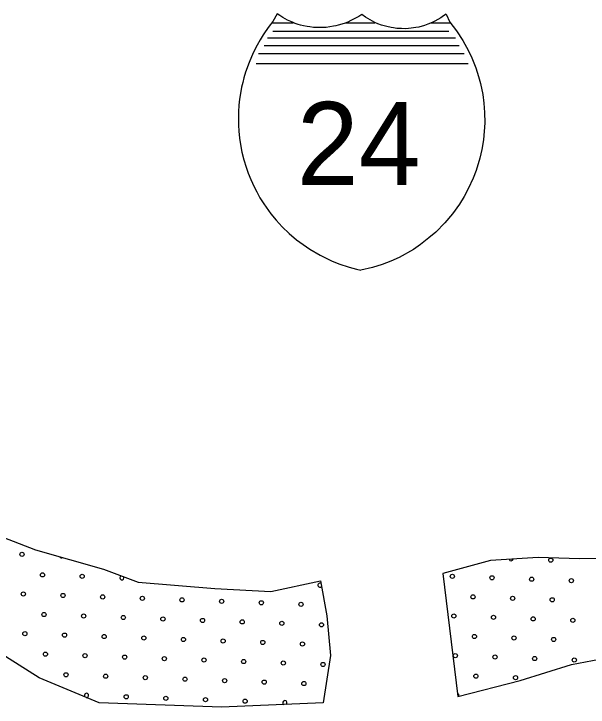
# Model space of a CAD drawing. Extents: x 1612280 to 1883141, y 560852 to 780851.
# Drawn here: x 1742163 to 1745083, y 665250 to 668775 of the extents above; entities that cross this region are included whole.
import ezdxf

# ---------------------------------------------------------------- set-up
doc = ezdxf.new("R2010")
doc.units = 0
for name, color, linetype in [('DESIGN - SCRATCH - User 1', 7, 'Continuous'), ('DESIGN - TRAFFIC CONTROL PERMANENT - Pavement Marking Text', 7, 'Continuous'), ('SURVEY - DRAINAGE - Bridge Hydraulic Data with Text', 7, 'Continuous')]:
    doc.layers.add(name, color=color, linetype=linetype)

msp = doc.modelspace()

# ---------------------------------------------------------------- linework, layer by layer
at = {"layer": 'DESIGN - SCRATCH - User 1'}
for points in [[(1741259.1, 666494.7), (1741480.4, 666378.9), (1741776.1, 666218.2), (1741969.5, 666167.1), (1742272.5, 666050.2), (1742619.3, 665951.5), (1742794.6, 665885.8), (1743185.2, 665852.9), (1743469.9, 665838.3), (1743721.8, 665893.1), (1743754.7, 665714.1), (1743772.9, 665513.2), (1743736.4, 665272.1)], [(1741259.1, 666494.7), (1741480.4, 666378.9), (1741776.1, 666218.2), (1741969.5, 666167.1), (1742272.5, 666050.2), (1742619.3, 665951.5), (1742794.6, 665885.8), (1743185.2, 665852.9), (1743469.9, 665838.3), (1743721.8, 665893.1), (1743754.7, 665714.1), (1743772.9, 665513.2), (1743736.4, 665272.1)], [(1747548.2, 666496.2), (1747291, 666404.3), (1747000.7, 666316), (1746600.2, 666238.8), (1746284.2, 666183.7), (1745913, 666113.8), (1745593.4, 666043.9), (1745281, 666007.2), (1745038.5, 666003.5), (1744829.1, 666010.8), (1744586.6, 665996.1), (1744344, 665930)], [(1747548.2, 666496.2), (1747291, 666404.3), (1747000.7, 666316), (1746600.2, 666238.8), (1746284.2, 666183.7), (1745913, 666113.8), (1745593.4, 666043.9), (1745281, 666007.2), (1745038.5, 666003.5), (1744829.1, 666010.8), (1744586.6, 665996.1), (1744344, 665930)], [(1743736.4, 665272.1), (1743218, 665250.2), (1742597.4, 665272.1), (1742290.8, 665399.9), (1742035.2, 665560.7), (1741710.3, 665714.1), (1741498.6, 665845.6), (1741327, 665988.1), (1741049.6, 666141.5), (1740797.8, 666308.4)], [(1743736.4, 665272.1), (1743218, 665250.2), (1742597.4, 665272.1), (1742290.8, 665399.9), (1742035.2, 665560.7), (1741710.3, 665714.1), (1741498.6, 665845.6), (1741327, 665988.1), (1741049.6, 666141.5), (1740797.8, 666308.4)], [(1744344, 665930), (1744421.2, 665304.9), (1744737.2, 665385.8), (1744998.1, 665466.7), (1745211.2, 665507.1), (1745475.8, 665521.8), (1745766.1, 665551.2), (1746008.6, 665562.3), (1746207, 665599), (1746570.8, 665691), (1746883.1, 665786.6), (1747129.3, 665867.5), (1747202.8, 665871.1), (1747246.9, 665819.7), (1747243.2, 665746.1), (1746971.3, 665569.6), (1746975, 665507.1), (1747133, 665389.5), (1747199.1, 665404.2), (1747415.9, 665507.1), (1747551.9, 665668.9), (1747493.1, 665760.8), (1747478.4, 665819.7)], [(1744344, 665930), (1744421.2, 665304.9), (1744737.2, 665385.8), (1744998.1, 665466.7), (1745211.2, 665507.1), (1745475.8, 665521.8), (1745766.1, 665551.2), (1746008.6, 665562.3), (1746207, 665599), (1746570.8, 665691), (1746883.1, 665786.6), (1747129.3, 665867.5), (1747202.8, 665871.1), (1747246.9, 665819.7), (1747243.2, 665746.1), (1746971.3, 665569.6), (1746975, 665507.1), (1747133, 665389.5), (1747199.1, 665404.2), (1747415.9, 665507.1), (1747551.9, 665668.9), (1747493.1, 665760.8), (1747478.4, 665819.7)]]:
    msp.add_lwpolyline(points, dxfattribs=at)
at = {"layer": 'DESIGN - TRAFFIC CONTROL PERMANENT - Pavement Marking Text'}
for centre in [(1742204, 666027.1), (1742204, 666027.1), (1744893.1, 665997.6), (1744893.1, 665997.6), (1742308.5, 665922.6), (1742308.5, 665922.6), (1742510.1, 665915.1), (1742510.1, 665915.1), (1744392.8, 665915.4), (1744392.8, 665915.4), (1744594.4, 665908), (1744594.4, 665908), (1744796, 665900.5), (1744796, 665900.5), (1744997.6, 665893), (1744997.6, 665893), (1742211.4, 665825.5), (1742211.4, 665825.5), (1742413, 665818), (1742413, 665818), (1742614.6, 665810.6), (1742614.6, 665810.6), (1742816.3, 665803.1), (1742816.3, 665803.1), (1743017.9, 665795.6), (1743017.9, 665795.6), (1744497.3, 665810.9), (1744497.3, 665810.9), (1744698.9, 665803.4), (1744698.9, 665803.4), (1744900.5, 665796), (1744900.5, 665796), (1743219.5, 665788.2), (1743219.5, 665788.2), (1743421.1, 665780.7), (1743421.1, 665780.7), (1743622.7, 665773.2), (1743622.7, 665773.2), (1742316, 665721), (1742316, 665721), (1742517.6, 665713.5), (1742517.6, 665713.5), (1742719.2, 665706), (1742719.2, 665706), (1742920.8, 665698.6), (1742920.8, 665698.6), (1743122.4, 665691.1), (1743122.4, 665691.1), (1744400.2, 665713.8), (1744400.2, 665713.8), (1744601.9, 665706.4), (1744601.9, 665706.4), (1744803.5, 665698.9), (1744803.5, 665698.9), (1745005.1, 665691.4), (1745005.1, 665691.4), (1743324, 665683.6), (1743324, 665683.6), (1743525.6, 665676.2), (1743525.6, 665676.2), (1743727.2, 665668.7), (1743727.2, 665668.7), (1742218.9, 665623.9), (1742218.9, 665623.9), (1742420.5, 665616.4), (1742420.5, 665616.4), (1742622.1, 665609), (1742622.1, 665609), (1742823.7, 665601.5), (1742823.7, 665601.5), (1743025.3, 665594), (1743025.3, 665594), (1743226.9, 665586.6), (1743226.9, 665586.6), (1744504.8, 665609.3), (1744504.8, 665609.3), (1744706.4, 665601.8), (1744706.4, 665601.8), (1744908, 665594.3), (1744908, 665594.3), (1743428.6, 665579.1), (1743428.6, 665579.1), (1743630.2, 665571.6), (1743630.2, 665571.6), (1742323.4, 665519.4), (1742323.4, 665519.4), (1742525, 665511.9), (1742525, 665511.9), (1744407.7, 665512.2), (1744407.7, 665512.2), (1742726.6, 665504.4), (1742726.6, 665504.4), (1742928.3, 665496.9), (1742928.3, 665496.9), (1743129.9, 665489.5), (1743129.9, 665489.5), (1743331.5, 665482), (1743331.5, 665482), (1743533.1, 665474.5), (1743533.1, 665474.5), (1744609.3, 665504.7), (1744609.3, 665504.7), (1744810.9, 665497.3), (1744810.9, 665497.3), (1745012.5, 665489.8), (1745012.5, 665489.8), (1743734.7, 665467.1), (1743734.7, 665467.1), (1742428, 665414.8), (1742428, 665414.8), (1742629.6, 665407.3), (1742629.6, 665407.3), (1744512.3, 665407.7), (1744512.3, 665407.7), (1742831.2, 665399.9), (1742831.2, 665399.9), (1743032.8, 665392.4), (1743032.8, 665392.4), (1743234.4, 665384.9), (1743234.4, 665384.9), (1743436, 665377.5), (1743436, 665377.5), (1743637.6, 665370), (1743637.6, 665370), (1744713.9, 665400.2), (1744713.9, 665400.2), (1742734.1, 665302.8), (1742734.1, 665302.8), (1742935.7, 665295.3), (1742935.7, 665295.3), (1743137.3, 665287.9), (1743137.3, 665287.9), (1743338.9, 665280.4), (1743338.9, 665280.4)]:
    msp.add_circle(centre, 10.6, dxfattribs=at)
for centre, start, end in [((1742405.6, 666019.6), 205.8254, 302.4248), ((1744691.5, 666005), 197.3402, 349.6011), ((1742711.7, 665907.6), 104.3943, 34.4671), ((1743719.8, 665870.3), 64.8213, 315.9818), ((1742532.5, 665310.3), 261.1113, 233.6226), ((1744415.2, 665310.6), 332.6234, 67.0315), ((1743540.6, 665272.9), 302.6487, 242.1934), ((1743742.2, 665265.5), 120.4637, 141.9596)]:
    msp.add_arc(centre, 10.6, start, end, dxfattribs=at)
at = {"layer": 'SURVEY - DRAINAGE - Bridge Hydraulic Data with Text'}
for p, q in [((1743475.7, 668730.2), (1743582.4, 668730.2)), ((1743475.7, 668730.2), (1743582.4, 668730.2)), ((1743851.6, 668730.2), (1743998.9, 668730.2)), ((1743851.6, 668730.2), (1743998.9, 668730.2)), ((1744284.3, 668730.2), (1744384.2, 668730.2)), ((1744284.3, 668730.2), (1744384.2, 668730.2)), ((1743479.7, 668687), (1744373.9, 668687)), ((1743479.7, 668687), (1744373.9, 668687)), ((1743452, 668653.1), (1744407.9, 668653.1)), ((1743452, 668653.1), (1744407.9, 668653.1)), ((1743435, 668614), (1744427, 668614.1)), ((1743435, 668614), (1744427, 668614.1)), ((1743407.3, 668573.7), (1744452.6, 668573.8)), ((1743407.3, 668573.7), (1744452.6, 668573.8)), ((1743395.6, 668523), (1744472.8, 668523)), ((1743395.6, 668523), (1744472.8, 668523))]:
    msp.add_line(p, q, dxfattribs=at)
for points in [[(1743502.4, 668775.4), (1743479.8, 668736.5), (1743460.8, 668712), (1743441.2, 668684.7), (1743430.8, 668669), (1743415.2, 668643.9), (1743399.4, 668616), (1743381.4, 668580.6), (1743370.5, 668557.1), (1743358.8, 668528.7), (1743340.9, 668478.2), (1743332.8, 668450.9), (1743326.6, 668426.9), (1743321.1, 668402.7), (1743314.9, 668369.6), (1743310.9, 668342.4), (1743307.4, 668310.6), (1743305.2, 668277.5), (1743304.4, 668238.3), (1743305, 668209.5), (1743306.8, 668179.3), (1743310.6, 668142.6), (1743315.2, 668111.8), (1743322.9, 668071.9), (1743332.4, 668033.4), (1743343.9, 667995.2), (1743354.1, 667966.1), (1743367.3, 667933.1), (1743384.1, 667896.2), (1743397.6, 667869.8), (1743414, 667840.7), (1743433.6, 667809.4), (1743469.4, 667759.2), (1743496.2, 667726.6), (1743527.1, 667692.8), (1743563.2, 667658), (1743600.7, 667626.1), (1743668, 667578.1), (1743719.7, 667547.8), (1743778.7, 667519.3), (1743814.7, 667504.8), (1743868, 667486.9), (1743904.8, 667477), (1743927.6, 667471.3)], [(1743502.4, 668775.4), (1743479.8, 668736.5), (1743460.8, 668712), (1743441.2, 668684.7), (1743430.8, 668669), (1743415.2, 668643.9), (1743399.4, 668616), (1743381.4, 668580.6), (1743370.5, 668557.1), (1743358.8, 668528.7), (1743340.9, 668478.2), (1743332.8, 668450.9), (1743326.6, 668426.9), (1743321.1, 668402.7), (1743314.9, 668369.6), (1743310.9, 668342.4), (1743307.4, 668310.6), (1743305.2, 668277.5), (1743304.4, 668238.3), (1743305, 668209.5), (1743306.8, 668179.3), (1743310.6, 668142.6), (1743315.2, 668111.8), (1743322.9, 668071.9), (1743332.4, 668033.4), (1743343.9, 667995.2), (1743354.1, 667966.1), (1743367.3, 667933.1), (1743384.1, 667896.2), (1743397.6, 667869.8), (1743414, 667840.7), (1743433.6, 667809.4), (1743469.4, 667759.2), (1743496.2, 667726.6), (1743527.1, 667692.8), (1743563.2, 667658), (1743600.7, 667626.1), (1743668, 667578.1), (1743719.7, 667547.8), (1743778.7, 667519.3), (1743814.7, 667504.8), (1743868, 667486.9), (1743904.8, 667477), (1743927.6, 667471.3)], [(1744360.8, 668774.1), (1744348.3, 668764.8), (1744333.8, 668755), (1744318.8, 668745.9), (1744302.8, 668737.4), (1744290.4, 668731.4), (1744268.6, 668722.4), (1744250.7, 668716.1), (1744222, 668708.4), (1744206.8, 668705.4), (1744182.3, 668701.9), (1744169.6, 668700.7), (1744153.5, 668700), (1744133.2, 668700.1), (1744124.7, 668700.5), (1744110.7, 668701.6), (1744093.7, 668703.7), (1744080.7, 668705.9), (1744059.9, 668710.5), (1744032.3, 668718.6), (1744014.2, 668725.4), (1743998.9, 668732), (1743974.7, 668744.3), (1743950.5, 668759.1), (1743931.6, 668772.8), (1743916.7, 668762.8), (1743897.1, 668751.3), (1743876.8, 668740.8), (1743861.2, 668733.9), (1743846.8, 668728.2), (1743830.5, 668722.7), (1743811.3, 668717.2), (1743799.3, 668714.2), (1743788.8, 668712), (1743769.7, 668708.9), (1743750.3, 668706.7), (1743736.4, 668705.8), (1743722.5, 668705.4), (1743704.2, 668705.7), (1743687.2, 668706.7), (1743667.9, 668708.9), (1743655, 668710.9), (1743635.9, 668714.8), (1743620.8, 668718.6), (1743609.1, 668722), (1743594.1, 668727), (1743582.4, 668731.4), (1743571.5, 668736), (1743554.2, 668744), (1743542, 668750.4), (1743530.8, 668756.7), (1743515.5, 668766.3), (1743502.4, 668775.4)], [(1744360.8, 668774.1), (1744348.3, 668764.8), (1744333.8, 668755), (1744318.8, 668745.9), (1744302.8, 668737.4), (1744290.4, 668731.4), (1744268.6, 668722.4), (1744250.7, 668716.1), (1744222, 668708.4), (1744206.8, 668705.4), (1744182.3, 668701.9), (1744169.6, 668700.7), (1744153.5, 668700), (1744133.2, 668700.1), (1744124.7, 668700.5), (1744110.7, 668701.6), (1744093.7, 668703.7), (1744080.7, 668705.9), (1744059.9, 668710.5), (1744032.3, 668718.6), (1744014.2, 668725.4), (1743998.9, 668732), (1743974.7, 668744.3), (1743950.5, 668759.1), (1743931.6, 668772.8), (1743916.7, 668762.8), (1743897.1, 668751.3), (1743876.8, 668740.8), (1743861.2, 668733.9), (1743846.8, 668728.2), (1743830.5, 668722.7), (1743811.3, 668717.2), (1743799.3, 668714.2), (1743788.8, 668712), (1743769.7, 668708.9), (1743750.3, 668706.7), (1743736.4, 668705.8), (1743722.5, 668705.4), (1743704.2, 668705.7), (1743687.2, 668706.7), (1743667.9, 668708.9), (1743655, 668710.9), (1743635.9, 668714.8), (1743620.8, 668718.6), (1743609.1, 668722), (1743594.1, 668727), (1743582.4, 668731.4), (1743571.5, 668736), (1743554.2, 668744), (1743542, 668750.4), (1743530.8, 668756.7), (1743515.5, 668766.3), (1743502.4, 668775.4)], [(1744360.8, 668774.1), (1744380.6, 668733.2), (1744413.7, 668689.7), (1744445.8, 668640.5), (1744474.6, 668588.1), (1744491.6, 668551.9), (1744511.8, 668500.9), (1744526.2, 668456.5), (1744535.5, 668421.7), (1744546.9, 668365.4), (1744552.9, 668320.9), (1744556.5, 668273.2), (1744557.1, 668221.1), (1744550.4, 668134.3), (1744542.4, 668086.3), (1744532, 668040.9), (1744513.3, 667979.6), (1744498.2, 667940.1), (1744473, 667885.1), (1744452.6, 667847.3), (1744428.3, 667808), (1744392.6, 667758.2), (1744354.2, 667712.5), (1744307.9, 667665.6), (1744273.8, 667635.8), (1744231, 667602.8), (1744194.2, 667577.9), (1744121.6, 667537.2), (1744079.4, 667517.8), (1744035.3, 667500.8), (1743986.7, 667485.4), (1743927.6, 667471.3)], [(1744360.8, 668774.1), (1744380.6, 668733.2), (1744413.7, 668689.7), (1744445.8, 668640.5), (1744474.6, 668588.1), (1744491.6, 668551.9), (1744511.8, 668500.9), (1744526.2, 668456.5), (1744535.5, 668421.7), (1744546.9, 668365.4), (1744552.9, 668320.9), (1744556.5, 668273.2), (1744557.1, 668221.1), (1744550.4, 668134.3), (1744542.4, 668086.3), (1744532, 668040.9), (1744513.3, 667979.6), (1744498.2, 667940.1), (1744473, 667885.1), (1744452.6, 667847.3), (1744428.3, 667808), (1744392.6, 667758.2), (1744354.2, 667712.5), (1744307.9, 667665.6), (1744273.8, 667635.8), (1744231, 667602.8), (1744194.2, 667577.9), (1744121.6, 667537.2), (1744079.4, 667517.8), (1744035.3, 667500.8), (1743986.7, 667485.4), (1743927.6, 667471.3)]]:
    msp.add_lwpolyline(points, dxfattribs=at)

# ---------------------------------------------------------------- texts
msp.add_text('24', height=422.41, rotation=0.0012, dxfattribs=at).set_placement((1743602.1, 667904.9))
msp.add_text('24', height=422.41, rotation=0.0012, dxfattribs=at).set_placement((1743602.1, 667904.9))

doc.saveas('drawing.dxf')
